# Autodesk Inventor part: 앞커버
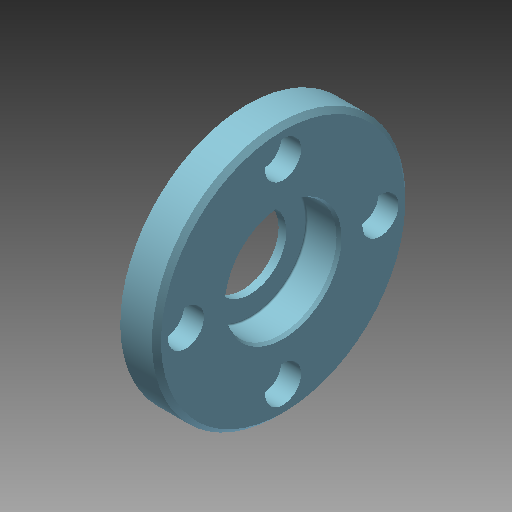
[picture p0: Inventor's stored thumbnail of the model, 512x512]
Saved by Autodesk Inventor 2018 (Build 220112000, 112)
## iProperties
Created: 2024-01
Part Number: 앞커버
Material: 알루미늄 6061
Document SubType Name: Modeling
Designer: mdu-01
Density: 1 g/cm^3
Appearance: 기본값(2)
Author: mdu-01
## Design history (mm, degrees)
sketch "스케치1"
  geometry: L1 (0, 0)-(-9, 0); L2 (-9, 0)-(-9, 14.5); L3 (-9, 14.5)-(-12, 14.5); L4 (-12, 14.5)-(-12, 16.5); L5 (-11, 17.5)-(-8, 17.5); L6 (-8, 17.5)-(-8, 28); L7 (-8, 28)-(-1, 28); L8 (0, 27)-(0, 0); L9 (-12, 16.5)-(-11, 17.5); L10 (-1, 28)-(0, 27); 2 further points
  constraints: 20 end point, 6 parallel, 4 point on line, 1 horizontal, 1 perpendicular
  dimensions: "d0" = 56 diameter of L7 L1; "d2" = 8 distance between parallel lines of L8 L6; "d3" = 3 distance between parallel lines of L2 L4; "d4" = 4 distance between parallel lines of L6 L4; "d5" = 29 diameter of L3 L1; "d6" = 35 diameter of L5 L1; "d7" = 1 distance of L4.end point (-12, 17.5); "d8" = 1 distance of L5.start point (-12, 17.5) (= d7); "d9" = 1 distance of L7.end point (0, 28) (= d7); "d10" = 1 distance of L8.start point (0, 28) (= d9)
revolve "회전1" sketch "스케치1" stored, may be unused: angle "d11" = 90 deg
sketch "스케치2" dims "d12" = 43
  geometry: 3 further points
  constraints: 2 vertical alignment, 1 coincident, 2 other
hole "구멍1" sketch "스케치2" at (0, 21.5) diameter "d13" = 4.5; stored, may be unused: countersink angle "d17" = 90 deg, drill point angle "d19" = 118 deg; dims "d14" = 6, "d15" = 8, "d16" = 4.4, "d18" = 8
sketch "스케치3"
  geometry: L1 (-9, -14.5)-(-9, 14.5) reference; L2 (0, -27)-(0, 27) reference; L3 (-9, 0)-(0, 0); L4 (0, 12.904)-(-0.7, 12.5); L5 (-0.7, 12.5)-(-7, 12.5); L6 (-7.3, 12.2)-(-7.3, 8); L7 (-7.3, 8)-(-9, 8); A1 r 0.3 centre (-7, 12.2) between (-7, 12.5) and (-7.3, 12.2)
  constraints: 10 end point, 3 perpendicular, 2 point on circle, 2 point on line, 2 tangent, 1 centre point, 1 midpoint, 1 parallel
  dimensions: "d23" = 30 deg angle of L5 L4; "d24" = 0.7 distance from line of L4.end L2; "d25" = 7.3 distance between parallel lines of L6 L2; "d26" = 25 diameter of L5 L3; "d27" = 0.3 radius of A1; "d28" = 16 diameter of L7 L3
revolve "회전2" sketch "스케치3" stored, may be unused: angle "d29" = 90 deg
node "솔리드1"
pattern_circular "원형 패턴1" dims angle "d21" = 360 deg
